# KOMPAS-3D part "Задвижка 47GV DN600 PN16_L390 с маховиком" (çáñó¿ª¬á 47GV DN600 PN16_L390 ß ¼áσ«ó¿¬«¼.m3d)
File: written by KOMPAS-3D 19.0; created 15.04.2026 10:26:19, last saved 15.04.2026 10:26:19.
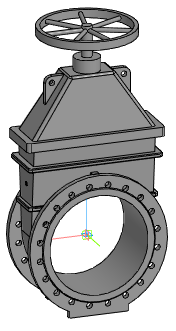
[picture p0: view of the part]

Document properties: Автор: Евгений; Полное имя файла: Z:\3.Личные\kachalov\3d для проектировщиков\2.1 Тип 47GV, 47GV.Z\Задвижка 47GV_DN40-DN600\stp_Задвижка 47GV\Задвижка 47GV DN600 PN16_L390 с маховиком.m3d

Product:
- Part/product: Задвижка 47GV DN600 PN16_L390 с маховиком

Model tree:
1. Операция без истории:1  (labels: Задвижка 47GV DN600 PN16_L390 с маховиком)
